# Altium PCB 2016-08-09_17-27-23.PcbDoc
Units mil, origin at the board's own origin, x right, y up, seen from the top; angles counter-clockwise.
Board outline 3000 x 3000 mil, 4 copper layers (Top Layer, MidLayer1, MidLayer2, Bottom Layer); 16 components, 10 nets, 35 pads, 23 vias.
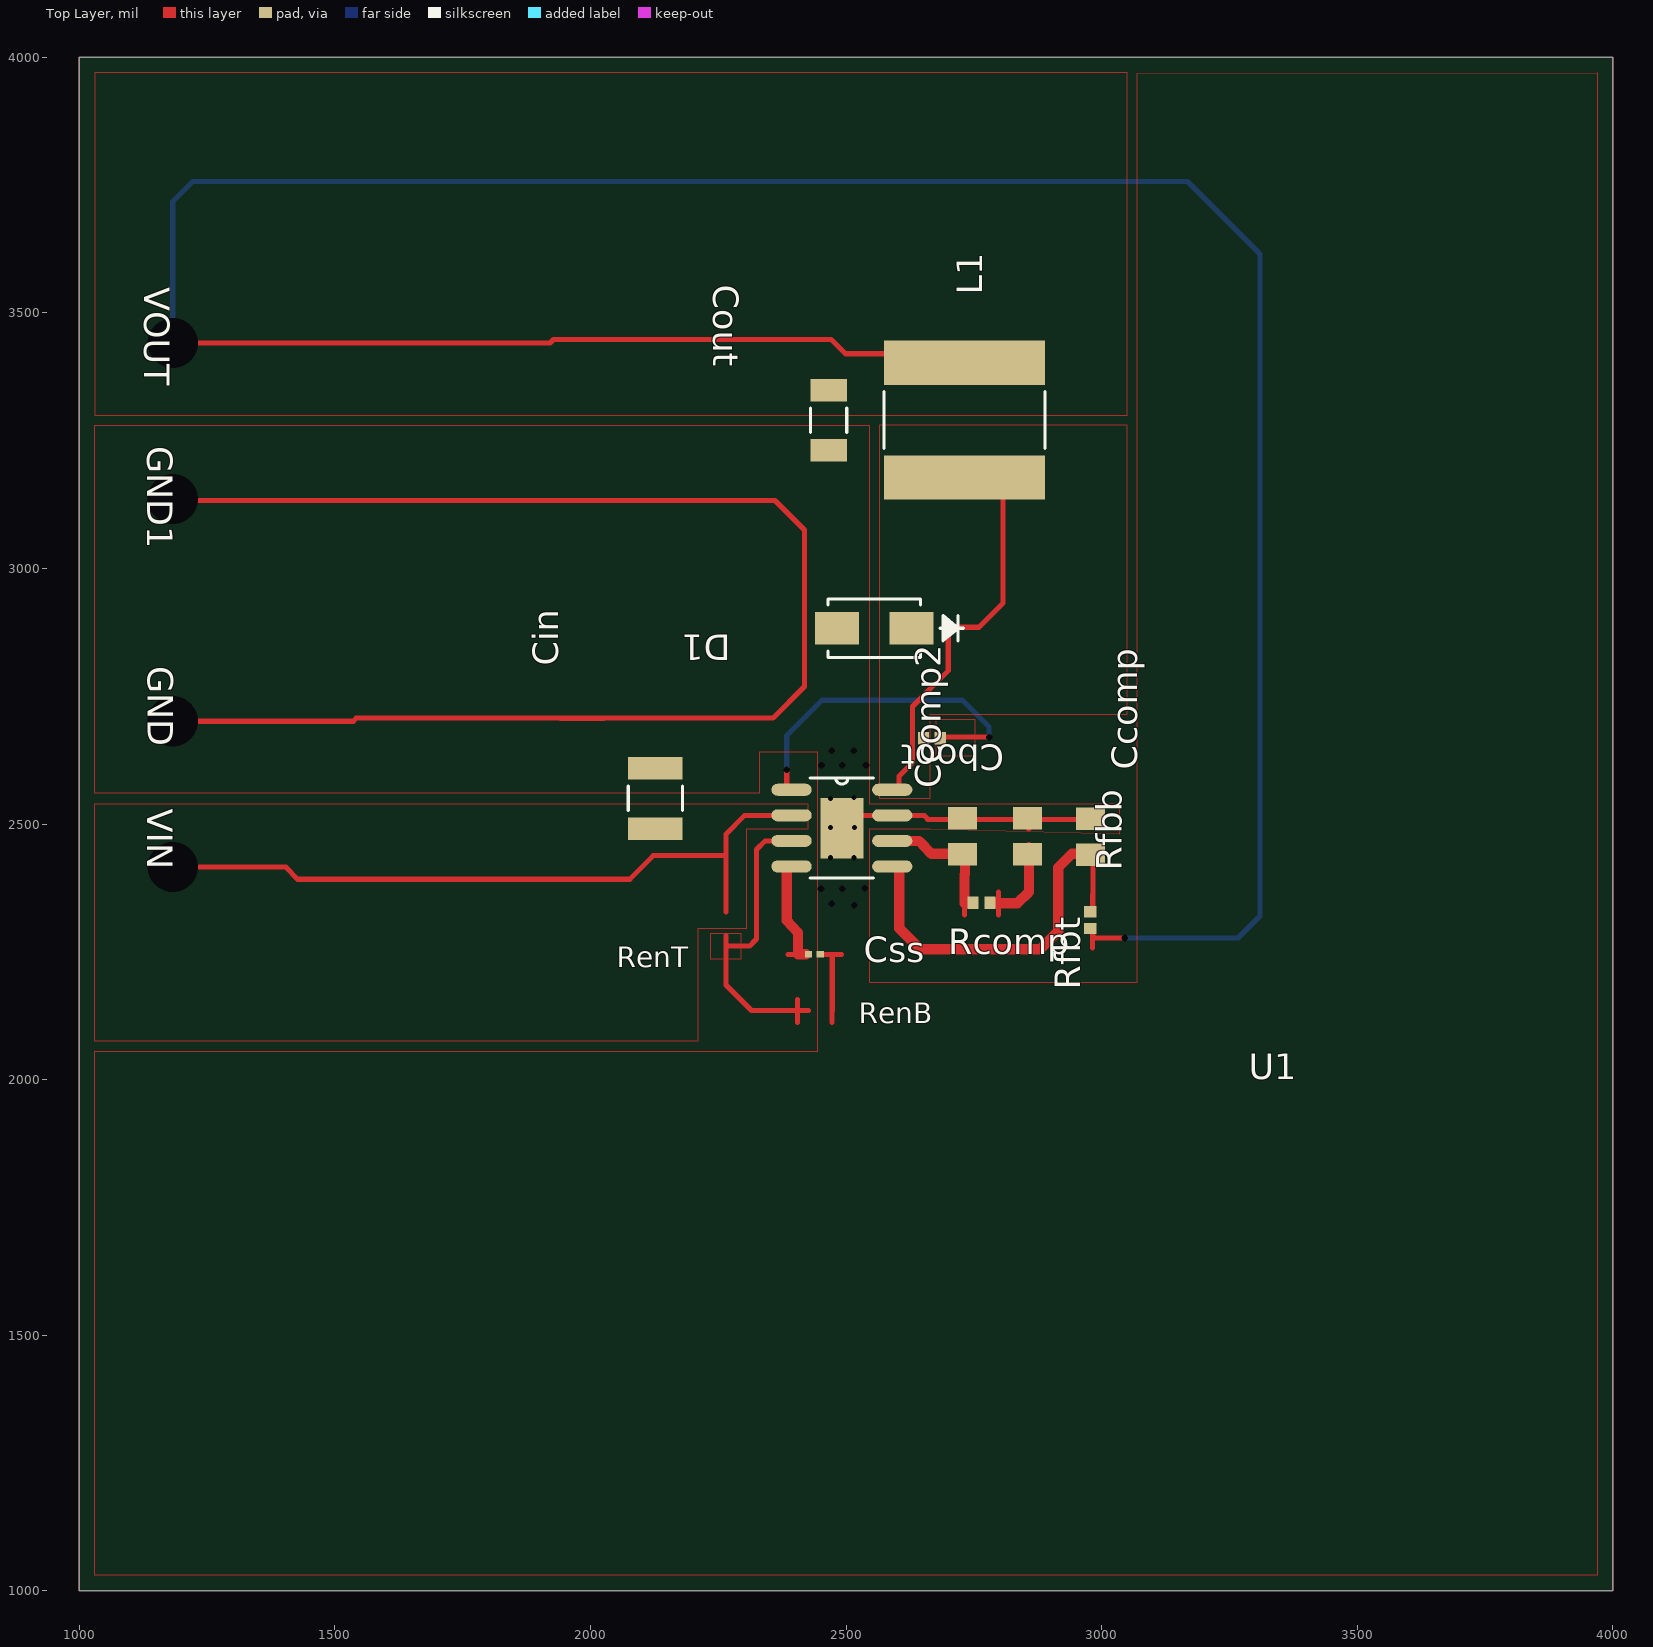
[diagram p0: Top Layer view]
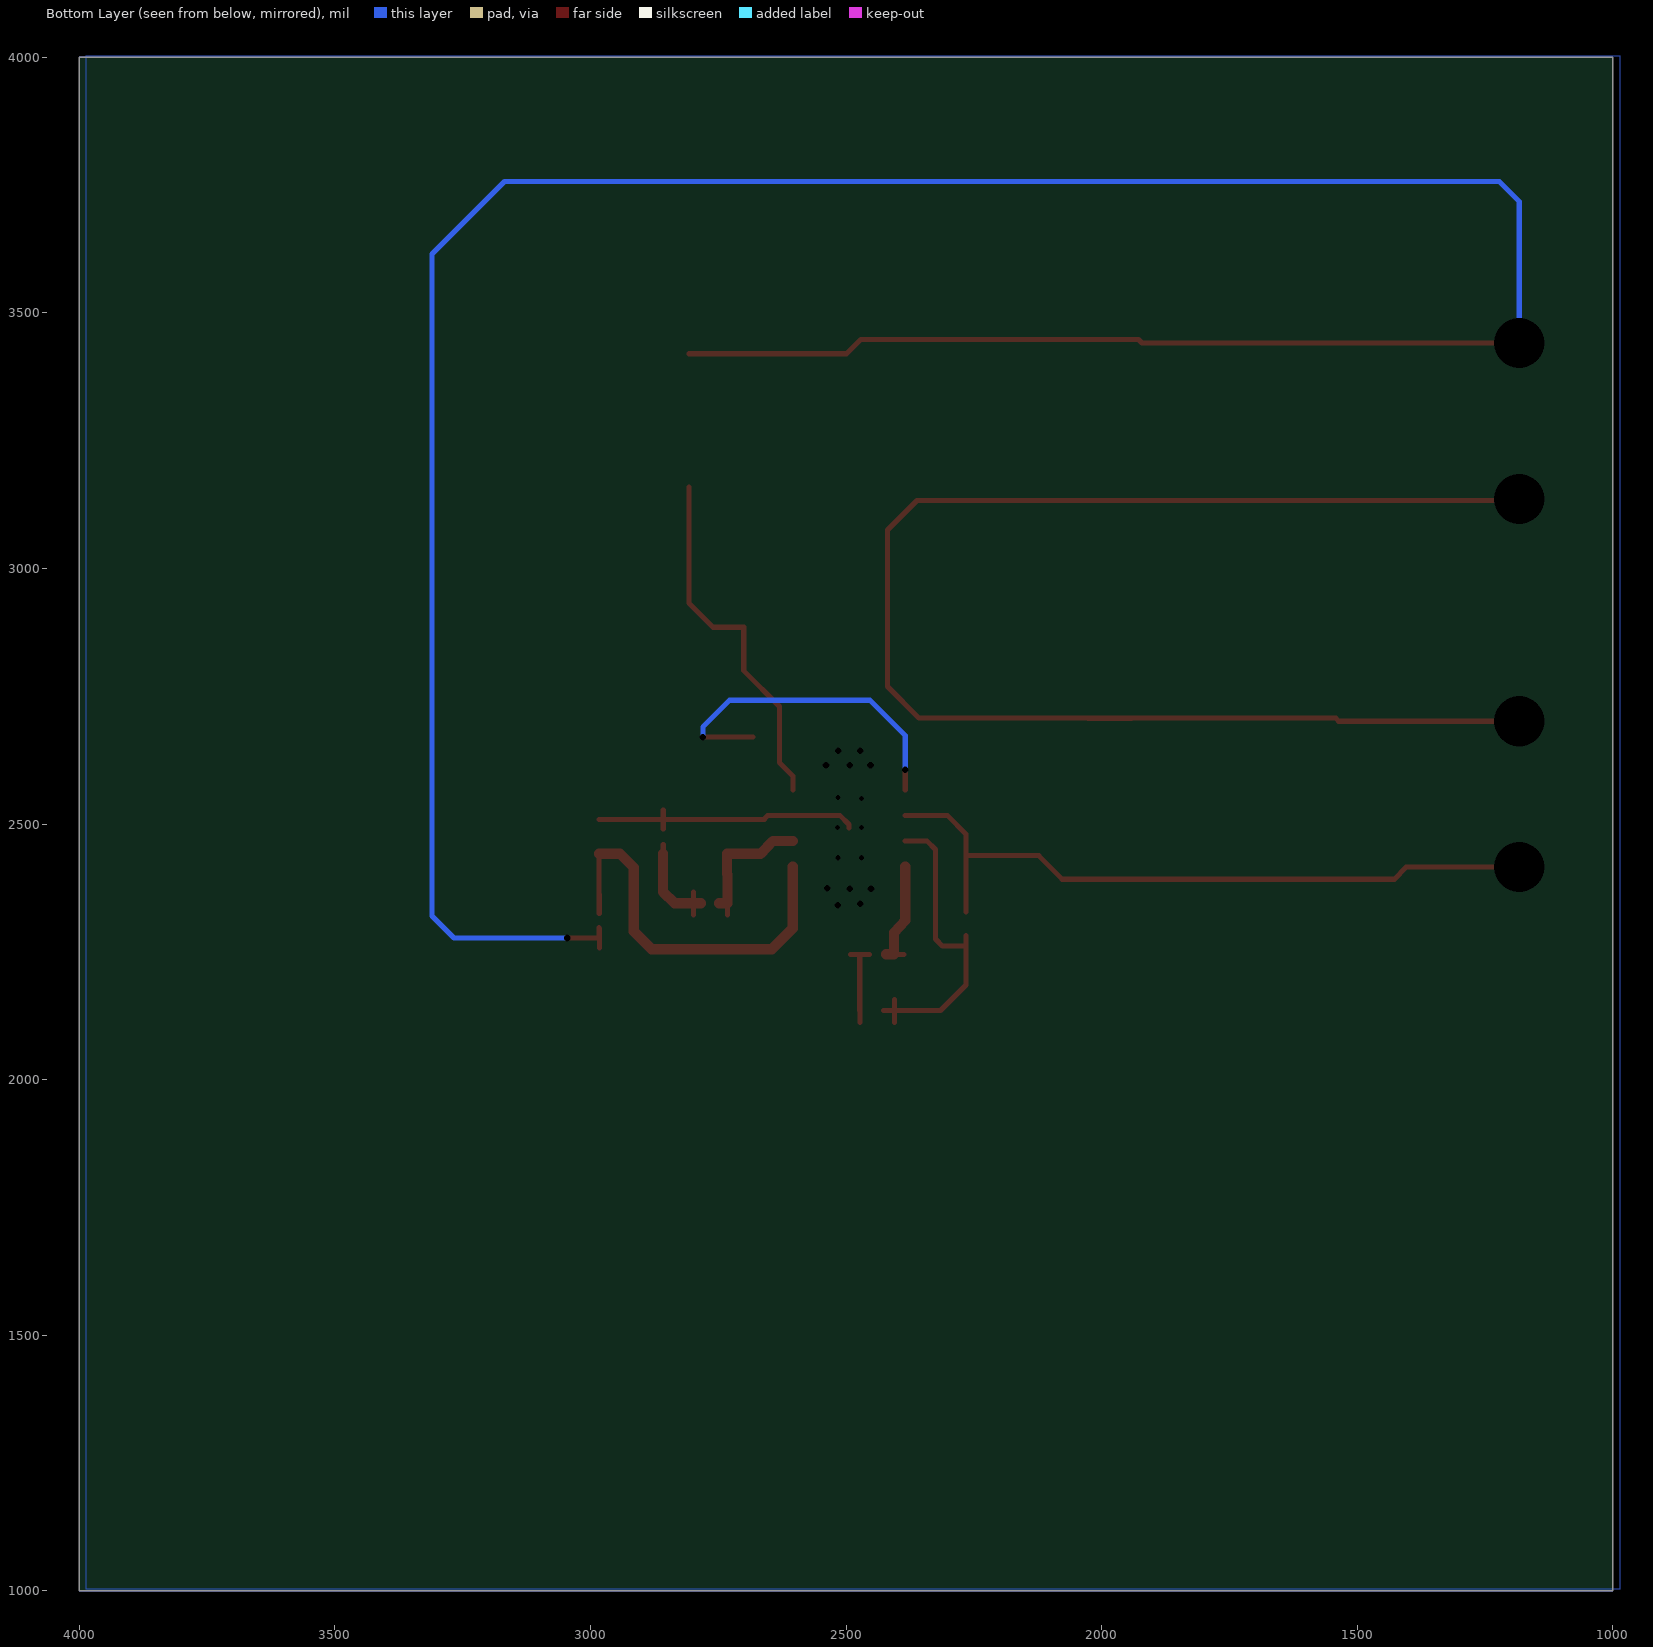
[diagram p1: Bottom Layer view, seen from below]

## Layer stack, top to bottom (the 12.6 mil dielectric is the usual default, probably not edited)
Top Layer: signal copper 1.4
Dielectric: core 12.6, FR-4, Dk 4.8
MidLayer1: signal copper 1.4
Dielectric: prepreg 12.6, FR-4, Dk 4.8
MidLayer2: signal copper 1.4
Dielectric: core 12.6, FR-4, Dk 4.8
Bottom Layer: signal copper 1.4

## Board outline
1000,1000 4000,1000 4000,4000 1000,4000

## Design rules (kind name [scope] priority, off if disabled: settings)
PlaneConnect [All] p0: scope1count=1 scope1_0_kind=Board scope1_0_value=Board scope2count=1 scope2_0_kind=Board scope2_0_value=Board commentlength=0 planeconnectstyle=Direct reliefexpansion=20 reliefentries=4 reliefconductorwidth=10 reliefairgap=10
PlaneConnect [All] p1: planeconnectstyle=Direct reliefexpansion=20 reliefentries=4 reliefconductorwidth=10 reliefairgap=10
PolygonConnect [All] p0: scope1count=1 scope1_0_kind=Board scope1_0_value=Board scope2count=1 scope2_0_kind=Board scope2_0_value=Board commentlength=0 connectstyle=Direct reliefconductorwidth=10 reliefentries=4 polygonreliefangle="90 Angle"
PolygonConnect [All] p1: connectstyle=Direct reliefconductorwidth=10 reliefentries=4 polygonreliefangle="90 Angle"

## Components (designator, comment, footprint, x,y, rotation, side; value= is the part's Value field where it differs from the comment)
Cboot "" 0402 2668,2668 r180 top
Ccomp "" 0805 2855,2476 r90 top
Ccomp2 "" 0805 2728,2476 r90 top
Cin "" 1210 2127,2550 r90 top
Cout "" 1206_190 2466,3290 r270 top
Css "" 0201 2438,2245 r0 top
D1 "" SMA 2555,2883 r180 top
GND "" TP-1502 1182,2700 r270 top
GND1 "" TP-1502 1182,3135 r270 top
L1 "" SRN8040 2732,3290 r90 top
Rcomp "" 0402 2765,2346 r0 top
Rfbb "" 0805 2978,2475 r90 top
Rfbt "" 0402 2978,2312 r90 top
U1 "" DDA0008H 2492,2492 r0 top
VIN "" TP-1502 1182,2413 r270 top
VOUT "" TP-1502 1182,3438 r270 top

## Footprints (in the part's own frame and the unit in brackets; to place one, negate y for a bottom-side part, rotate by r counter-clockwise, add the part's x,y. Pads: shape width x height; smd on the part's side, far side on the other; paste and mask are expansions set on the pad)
0201 [mil]
  rect 14x13 smd: 1(-11.5,0) 2(11.5,0)
0402 [mil]
  rect 22x24 smd: 1(-16.5,0) 2(16.5,0)
0805 [mil]
  rect 44x57 smd: 1(-35.5,0) 2(35.5,0)
1206_190 [mil]
  rect 44x71 smd: 1(-59,0) 2(59,0)
  silkscreen extent -24,-36 24,36
1210 [mil]
  rect 44x106 smd: 1(-59,0) 2(59,0)
  silkscreen extent -24,-53 24,53
DDA0008H [mm]
  oval 2x0.6 smd: 1(-2.5,1.905) 2(-2.5,0.635) 3(-2.5,-0.635) 4(-2.5,-1.905) 5(2.5,-1.905) 6(2.5,-0.635) 7(2.5,0.635) 8(2.5,1.905)
  rect 2.13x3 smd: 9(0,0)
  silkscreen extent -1.58,-2.49 1.58,2.49
SMA [mil]
  rect 86x64 smd: 1(-73,0) 2(73,0)
  silkscreen extent -174,-58 90,58
SRN8040 [mm]
  rect 2.2x8 smd: 1(-2.85,0) 2(2.85,0)
  silkscreen extent -1.42,-4 1.42,4
TP-1502 [mil]
  round 65 / inner round 0 / far side round 65 hole 32: 1(0,0)

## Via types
v1: diameter 0, hole 13, Top Layer to Bottom Layer, 13 vias
v2: diameter 0, hole 10, Top Layer to Bottom Layer, 6 vias
v3: diameter 0, hole 98, Top Layer to Bottom Layer, 4 vias

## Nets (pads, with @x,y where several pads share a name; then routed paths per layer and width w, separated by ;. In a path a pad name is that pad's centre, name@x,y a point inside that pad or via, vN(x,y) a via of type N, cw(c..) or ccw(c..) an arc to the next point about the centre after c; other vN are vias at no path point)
0: Ccomp2.2 Ccomp.2 Cin.2 Cout.2 Css.2 D1.2 GND1.1 GND.1 Rfbb.2 U1.7 U1.9 | length 3651.9
  Top Layer w10: v3(1183,2701) 1536,2701 1542,2707 1985,2707 2357,2707 2419,2769 2419,2885 2419,3075 2361,3133 2303,3133 1185,3133 v3(1183,3136) ; 1942,2706.5 2026,2706.5 ; Css.2@2454,2244.5 2491,2244.5 ; 2472.5,2112 2472.5,2157 ; 2473,2135 2473,2245 ; U1.9@2494,2492 2494,2499 2512,2517 2604,2517 2653,2517 2660,2509 2733,2509 2780,2509 2858,2509 Rfbb.2@2983,2509 ; Ccomp.2@2857.5,2490 Ccomp.2@2857.5,2527
  other v1: 2516,2341 2472,2344 2451,2373 2493,2373 2537,2374 2452,2615 2493,2615 2539,2615 2472,2643 2515,2643
  other v2: 2470,2434 2516,2434 2470,2493 2517,2493 2470,2550 2516,2552
1: Cin.1 U1.2 VIN.1 | length 1481.6
  Top Layer w10: v3(1183,2416) 1404,2416 1427,2392 1985,2392 2077,2392 2123,2438 2265,2438 ; 1942,2391.5 2026,2391.5 ; 2265,2328 2265,2438 ; U1.2@2384,2517 2302,2517 2265,2480 2265,2438
2: Ccomp2.1 Rcomp.1 U1.6 | length 298.1
  Top Layer w10: 2731.5,2322 2731.5,2367
  Top Layer w20: U1.6@2604,2467 2643,2467 2667,2442 2733,2442 2733,2402 2732,2401 2732,2345 Rcomp.1@2748,2345
3: Css.1 U1.4 | length 233.8
  Top Layer w10: 2387,2244.5 Css.1@2424,2244.5
  Top Layer w20: U1.4@2384,2417 2384,2311 2406,2288 2406,2245 Css.1@2422,2245
4: Cboot.2 D1.1 L1.2 U1.8 | length 711.2
  Top Layer w10: U1.8@2604,2567 2604,2594 2630,2620 2630,2670 2630,2730 2700,2800 2700,2885 2760,2885 2807,2932 2807,3159
5: Rfbb.1 Rfbt.2 U1.5 | length 821.7
  Top Layer w10: Rfbt.2@2982.5,2325 2982.5,2362 ; Rfbt.2@2983,2325 2983,2344 Rfbb.1@2983,2442
  Top Layer w20: U1.5@2604,2417 2604,2296 2645,2255 2880,2255 2915,2290 2915,2415 2942,2442 Rfbb.1@2983,2442
6: Cout.1 L1.1 Rfbt.1 VOUT.1 | length 5814.3
  Top Layer w10: v3(1183,3441) 1921,3441 1928,3448 2303,3448 2471,3448 2499,3420 2807,3420 ; 2982.5,2258 Rfbt.1@2982.5,2295 ; Rfbt.1@2983,2297 2983,2277 v1(3045,2277)
  Bottom Layer w10: v3(1183,3441) 1183,3718 1222,3757 3168,3757 3310,3615 3310,2320 3267,2277 v1(3045,2277)
7: Ccomp.1 Rcomp.2 | length 239.8
  Top Layer w10: 2798.5,2322 2798.5,2367 ; Ccomp.1@2857.5,2423 Ccomp.1@2857.5,2460
  Top Layer w20: Rcomp.2@2784,2345 2799,2345 2835,2345 2858,2367 Ccomp.1@2858,2442
8: Cboot.1 U1.1 | length 670.1
  Top Layer w10: U1.1@2384,2567 v1(2384,2606) ; Cboot.1@2682,2670 2710,2670 v1(2780,2670)
  Bottom Layer w10: v1(2384,2606) 2384,2673 2453,2742 2728,2742 2780,2690 v1(2780,2670)
11: U1.3 | length 631.6
  Top Layer w10: 2265,2282 2265,2261 ; U1.3@2384,2467 2342,2467 2325,2450 2325,2275 2311,2261 2265,2261 ; 2405.5,2112 2405.5,2157 ; 2427,2135 2406,2135 2315,2135 2265,2185 2265,2261

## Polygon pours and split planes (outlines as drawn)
11 on Top Layer " " (solid, pour order 0): 2235,2235 2235,2286 2294,2286 2294,2235
8 on Top Layer " " (solid, pour order 1): 2677,2633 2677,2705 2752,2705 2752,2633
4 on Top Layer " " (solid, pour order 2): 2565,2550 2665,2550 2665,2715 3050,2715 3050,3280 2565,3280
6 on Top Layer " " (solid, pour order 3): 3050,3300 3050,3970 1030,3970 1030,3300
1 on Top Layer " " (solid, pour order 4): 1030,2540 2425,2540 2425,2490 2305,2490 2305,2295 2210,2295 2210,2075 1030,2075
0 on Top Layer " " (solid, pour order 5): 1030,3280 2545,3280 2545,2540 3035,2540 3035,2480 2665,2490 2545,2490 2545,2190 3070,2190 3070,3969 3970,3970 3970,1030 1030,1030 1030,2055 2445,2055 2445,2640 2330,2640 2330,2560 1030,2560
0 on Bottom Layer " " (solid, pour order 8): 986,4003 986,1003 3986,1003 3986,4003
0 on MidLayer1 " " (solid, pour order 6): 1030,3970 1030,1030 3970,1030 3970,3970
0 on MidLayer2 " " (solid, pour order 7): 1030,3970 1030,1030 3970,1030 3970,3970

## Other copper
Multi-Layer:
  the board outline again, w1

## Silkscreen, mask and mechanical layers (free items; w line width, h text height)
Top Overlay:
  text "RenT" at 2052,2220 h40
  text "RenB" at 2525,2110 h40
